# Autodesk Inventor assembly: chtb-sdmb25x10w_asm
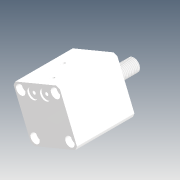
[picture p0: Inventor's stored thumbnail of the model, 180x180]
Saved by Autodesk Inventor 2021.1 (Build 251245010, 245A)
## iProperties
Company: Microsoft
Created: 2018-05
Part Number: chtb-sdmb25x10w_asm
Description: STEP AP214
Document SubType Name: Assembly
Designer: user
Title: chtb-sdmb25x10w_asm.STEP
Author: Windows
Revision Number: ÈÎºÎ
Sending System: SolidWorks 2015
Preprocessor: SwSTEP 2.0
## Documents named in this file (4)
- D:\Vault_2016\Projekty\Clamptek\Hydraulic\CHTB\CHTB-25\Inventor\chtb-sdmb25x10w\chtb-sdmb25x10w_asm.iam
- D:\Vault_2016\Projekty\Clamptek\Hydraulic\CHTB\CHTB-25\Inventor\chtb-sdmb25x10w\CHTB-25QG.ipt
- D:\Vault_2016\Projekty\Clamptek\Hydraulic\CHTB\CHTB-25\Inventor\chtb-sdmb25x10w\CHTB-SDMB25X10NBT.ipt
- D:\Vault_2016\Projekty\Clamptek\Hydraulic\CHTB\CHTB-25\Inventor\chtb-sdmb25x10w\CHTB-SDMB25X10WHSG.ipt
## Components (3 placed, 3 different names)
1. CHTB-25QG_1
2. CHTB-SDMB25X10NBT_2
3. CHTB-SDMB25X10WHSG_3
